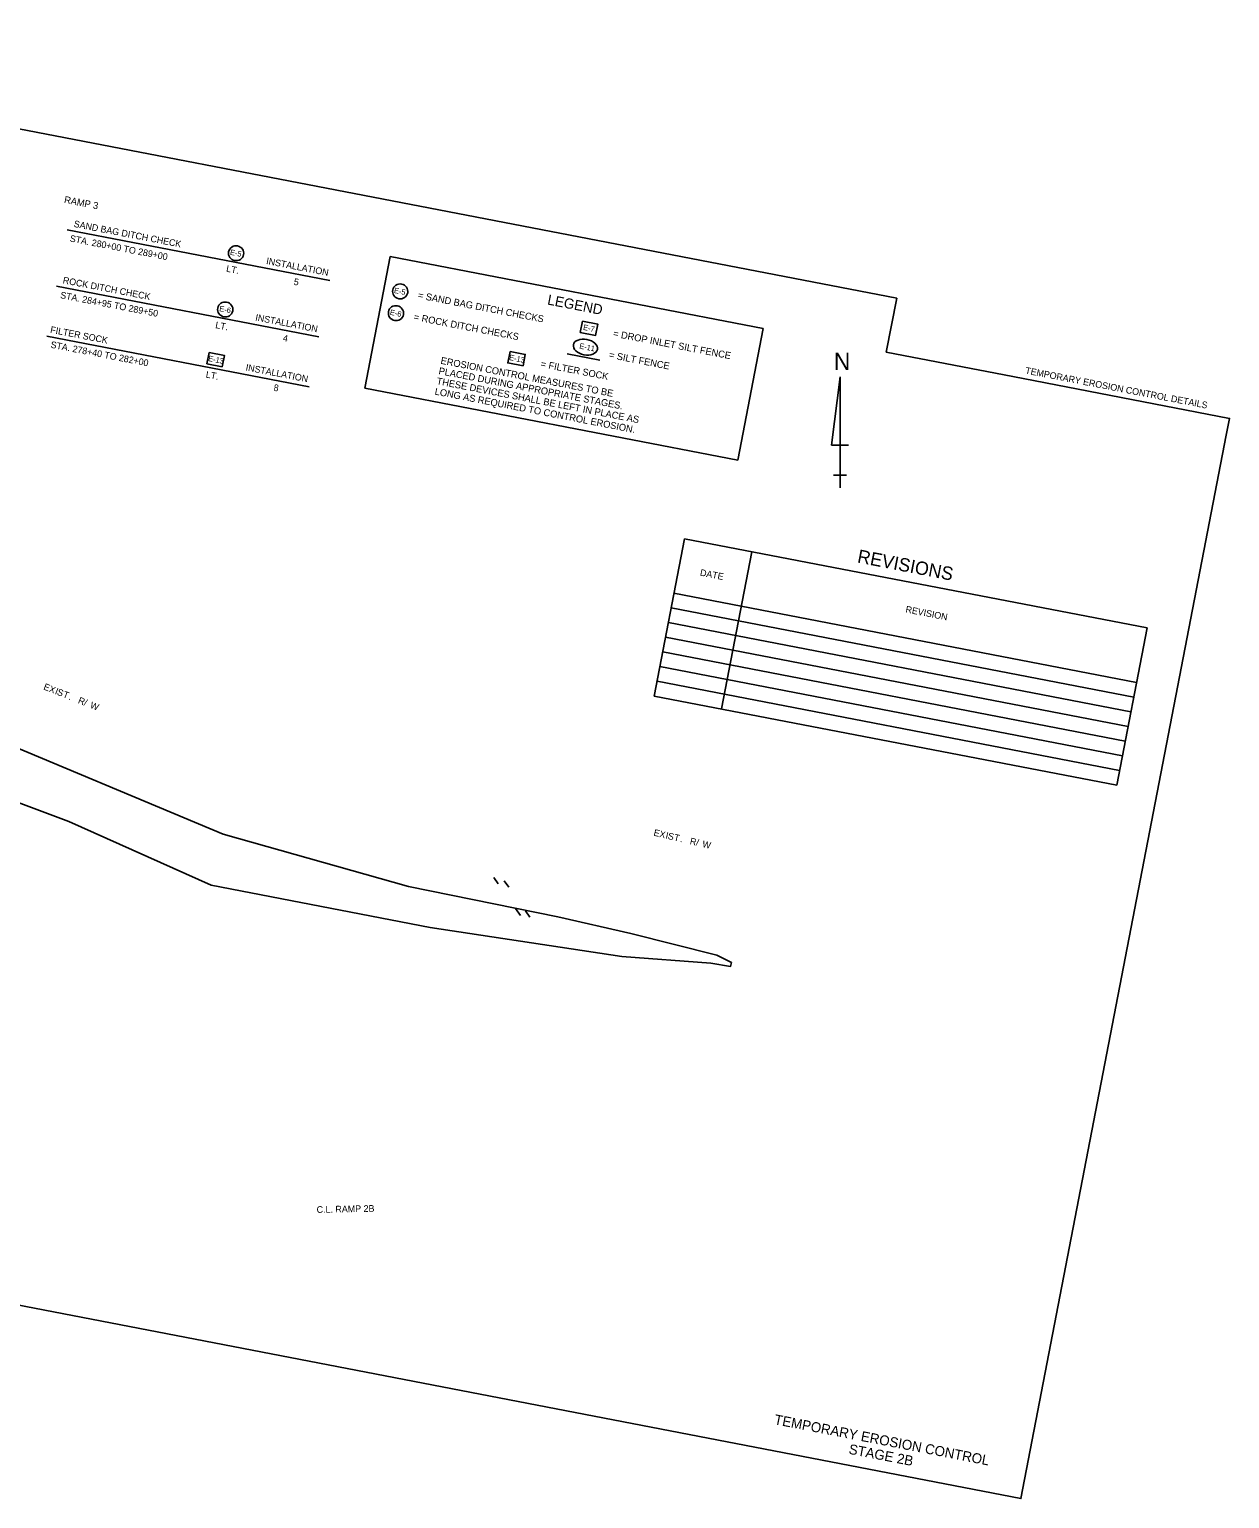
# Model space of a CAD drawing. Extents: x 610464 to 612219, y 418975 to 420301.
# Drawn here: x 611136 to 612219, y 418975 to 420301 of the extents above; entities that cross this region are included whole.
import ezdxf

# ---------------------------------------------------------------- set-up
doc = ezdxf.new("R2010")
doc.units = 0
for name, color, linetype in [('Plan Notes', 7, 'Continuous'), ('R_Draft', 7, 'Continuous'), ('R_Island', 7, 'Continuous'), ('R_OBLI_EXIST', 7, 'Continuous'), ('R_Opt1 Proposed Rural', 7, 'Continuous'), ('X_Phi Angle_SB', 7, 'Continuous')]:
    doc.layers.add(name, color=color, linetype=linetype)

msp = doc.modelspace()

# ---------------------------------------------------------------- linework, layer by layer
for points in [[(610661.8, 420300.9), (611918.6, 420058.3), (611909.2, 420009.6), (612023.4, 419987.6), (612218.9, 419949.8), (612215.9, 419934.6), (612030.7, 418975.1), (610464.3, 419277.4)], [(610807.4, 419730.5), (610796.9, 419735.1), (610780.6, 419750.8), (610764.8, 419742.9), (610759.3, 419760.5), (610766.2, 419770.9), (610826.5, 419779.1), (610901, 419746), (611086.6, 419668.4), (611311.1, 419574.6), (611478.1, 419527.3), (611612.9, 419500), (611678.9, 419484.9), (611756.4, 419465.5), (611769.5, 419458.8), (611768.7, 419455.3), (611750.9, 419458.3), (611670.6, 419464.3), (611497.9, 419490.5), (611300.1, 419528.7), (611171.8, 419586.2), (611002.2, 419649.5), (610871.2, 419698)]]:
    msp.add_lwpolyline(points, close=True)
at = {"layer": 'Plan Notes'}
msp.add_lwpolyline([(611621.2, 420008), (611650.7, 420002.3)], dxfattribs=at)
at = {"layer": 'R_Island'}
for p, q in [((611170.4, 420119.9), (611407.1, 420074.2)), ((611160.6, 420069.1), (611397.3, 420023.4)), ((611151.9, 420023.9), (611388.6, 419978.2))]:
    msp.add_line(p, q, dxfattribs=at)
at = {"layer": 'R_OBLI_EXIST'}
for p, q in [((611559.1, 419529.9), (611555.2, 419535.5)), ((611568.6, 419526.9), (611564.6, 419532.6)), ((611574.8, 419507.6), (611579.1, 419501.4)), ((611587.7, 419499.8), (611583.7, 419505.4))]:
    msp.add_line(p, q, dxfattribs=at)
at = {"layer": 'R_Opt1 Proposed Rural'}
for p, q in [((611438.8, 419977.1), (611461.7, 420096)), ((611461.7, 420096), (611798.2, 420031.1)), ((611798.2, 420031.1), (611775.2, 419912.2)), ((611867.5, 419987.2), (611859.8, 419925.7)), ((611867.5, 419887.2), (611867.5, 419987.2)), ((611867.5, 419987.2), (611867.5, 419910.3)), ((611775.2, 419912.2), (611438.8, 419977.1)), ((611859.8, 419925.7), (611875.2, 419925.7)), ((611867.5, 419887.2), (611867.5, 419910.3)), ((611867.5, 419898.7), (611861.7, 419898.7)), ((611861.7, 419898.7), (611873.3, 419898.7)), ((611867.5, 419887.2), (611867.5, 419898.7)), ((611699.8, 419699.3), (611727.2, 419841.2)), ((611727.2, 419841.2), (612144.5, 419760.7)), ((611787.9, 419829.5), (611760.5, 419687.6)), ((611717.7, 419792.1), (612135, 419711.6)), ((611715.2, 419778.9), (612132.4, 419698.3)), ((611712.6, 419765.6), (612129.9, 419685.1)), ((611710, 419752.4), (612127.3, 419671.8)), ((611710, 419752.4), (612127.3, 419671.8)), ((612144.5, 419760.7), (612117.1, 419618.8)), ((611707.5, 419739.1), (612124.8, 419658.6)), ((611704.9, 419725.8), (612122.2, 419645.3)), ((611702.4, 419712.6), (612119.7, 419632)), ((612117.1, 419618.8), (611699.8, 419699.3))]:
    msp.add_line(p, q, dxfattribs=at)
for points in [[(611635.1, 420037.7), (611648.9, 420035), (611646.9, 420024.7), (611633.1, 420027.4)], [(611298.3, 420009.4), (611312.1, 420006.7), (611310.1, 419996.4), (611296.3, 419999.1)], [(611569.8, 420010.3), (611583.5, 420007.6), (611581.5, 419997.3), (611567.8, 419999.9)]]:
    msp.add_lwpolyline(points, close=True, dxfattribs=at)
for centre, major_axis, ratio in [((611322.7, 420098.9), (-6.76, 1.31), 0.97521), ((611470.7, 420064.4), (-6.76, 1.31), 0.97521), ((611312.9, 420048.1), (-6.76, 1.31), 0.97521), ((611466.9, 420044.8), (-6.76, 1.31), 0.97521), ((611637.8, 420014.2), (10.8, -2.1), 0.638788)]:
    msp.add_ellipse(centre, major_axis=major_axis, ratio=ratio, dxfattribs=at)

# ---------------------------------------------------------------- texts
at = {"layer": 'R_Draft'}
for s, rotation, p in [('E', 338.4521, (611148.4, 419705.4)), ('X', 338.4521, (611153.4, 419703.4)), ('I', 338.4521, (611158.8, 419701.3)), ('S', 338.4521, (611160.6, 419700.6)), ('T', 338.4521, (611165.9, 419698.5)), ('.', 338.4521, (611171.3, 419696.3)), ('R', 338.4521, (611179.6, 419693.1)), ('/', 338.4521, (611184.9, 419691)), ('W', 338.4521, (611190.4, 419688.8)), ('E', 346.8534, (611698.9, 419573.4)), ('X', 346.8534, (611704.1, 419572.1)), ('I', 346.8534, (611709.7, 419570.8)), ('S', 346.8534, (611711.7, 419570.4)), ('T', 346.8534, (611717.2, 419569.1)), ('.', 346.8534, (611722.9, 419567.7)), ('R', 346.8534, (611731.6, 419565.7)), ('/', 346.8534, (611737.1, 419564.4)), ('W', 346.8534, (611742.8, 419563.1)), ('C.L. RAMP 2B', 1.1692, (611395.4, 419232.9))]:
    msp.add_text(s, height=6, rotation=rotation, dxfattribs=at).set_placement(p)
at = {"layer": 'R_Island'}
for s, height, p in [('RAMP 3', 6.25, (611167.2, 420144.4)), ('SAND BAG DITCH CHECK', 6, (611175.9, 420122.7)), ('STA. 280+00 TO 289+00', 6, (611172.3, 420109.5)), ('INSTALLATION ', 6, (611349.5, 420089.2)), ('LT. ', 6, (611313.4, 420082.3)), ('ROCK DITCH CHECK', 6, (611166, 420071.8)), ('5', 6, (611374.3, 420070.5)), ('STA. 284+95 TO 289+50', 6, (611163.7, 420058.4)), ('INSTALLATION ', 6, (611339.7, 420038.3)), ('FILTER SOCK', 6, (611154.7, 420027.2)), ('LT. ', 6, (611303.6, 420031.4)), ('STA. 278+40 TO 282+00', 6, (611155, 420013.7)), ('4', 6, (611364.5, 420019.6)), ('LT. ', 6, (611295, 419986.8)), ('INSTALLATION ', 6, (611331, 419993.2)), ('TEMPORARY EROSION CONTROL DETAILS', 6, (612034.2, 419990.3)), ('8', 6, (611356.1, 419974.9)), ('TEMPORARY EROSION CONTROL ', 9, (611807.6, 419042.3)), ('STAGE 2B', 9, (611874.8, 419015.6))]:
    msp.add_text(s, height=height, rotation=349.0745, dxfattribs=at).set_placement(p)
at = {"layer": 'R_Opt1 Proposed Rural'}
for s, height, rotation, p in [('E-5', 4.88, 349.0745, (611316.9, 420097.6)), ('E-5', 4.88, 349.0745, (611464.8, 420063.1)), ('= SAND BAG DITCH CHECKS', 6.25, 349.0745, (611486.3, 420058.2)), ('LEGEND', 9.14, 349.0745, (611603, 420052.7)), ('E-6', 4.88, 349.0745, (611307.2, 420046.7)), ('E-6', 4.88, 349.0745, (611461.1, 420043.4)), ('= ROCK DITCH CHECKS', 6.25, 349.0745, (611482.5, 420038.6)), ('E-7', 5, 348.6922, (611635.4, 420029.8)), ('E-11', 5, 349.0745, (611632, 420012.9)), ('E-13', 5, 348.6922, (611297.2, 420001.7)), ('EROSION CONTROL MEASURES TO BE', 6.25, 349.0745, (611506.8, 419999.2)), ('E-13', 5, 348.6922, (611568.7, 420002.6)), ('N', 15.4, 360, (611861.9, 419993.6)), ('PLACED DURING APPROPRIATE STAGES. ', 6.25, 349.0745, (611505, 419989.9)), ('LONG AS REQUIRED TO CONTROL EROSION.', 6.25, 349.0745, (611501.5, 419971.4)), ('THESE DEVICES SHALL BE LEFT IN PLACE AS ', 6.25, 349.0745, (611503.2, 419980.7)), ('REVISIONS', 12, 349.0745, (611882.5, 419819.9)), ('DATE', 6, 349.0745, (611740.8, 419808)), ('REVISION', 6, 349.0745, (611926.2, 419774.8))]:
    msp.add_text(s, height=height, rotation=rotation, dxfattribs=at).set_placement(p)
at = {"layer": 'X_Phi Angle_SB'}
for s, p in [('= DROP INLET SILT FENCE', (611662.4, 420023.7)), ('= FILTER SOCK', (611597, 419996.2)), ('= SILT FENCE', (611658.6, 420004.4))]:
    msp.add_text(s, height=6.25, rotation=349.0745, dxfattribs=at).set_placement(p)

doc.saveas('drawing.dxf')
